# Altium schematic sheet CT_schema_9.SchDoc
size 277 x 170 mm
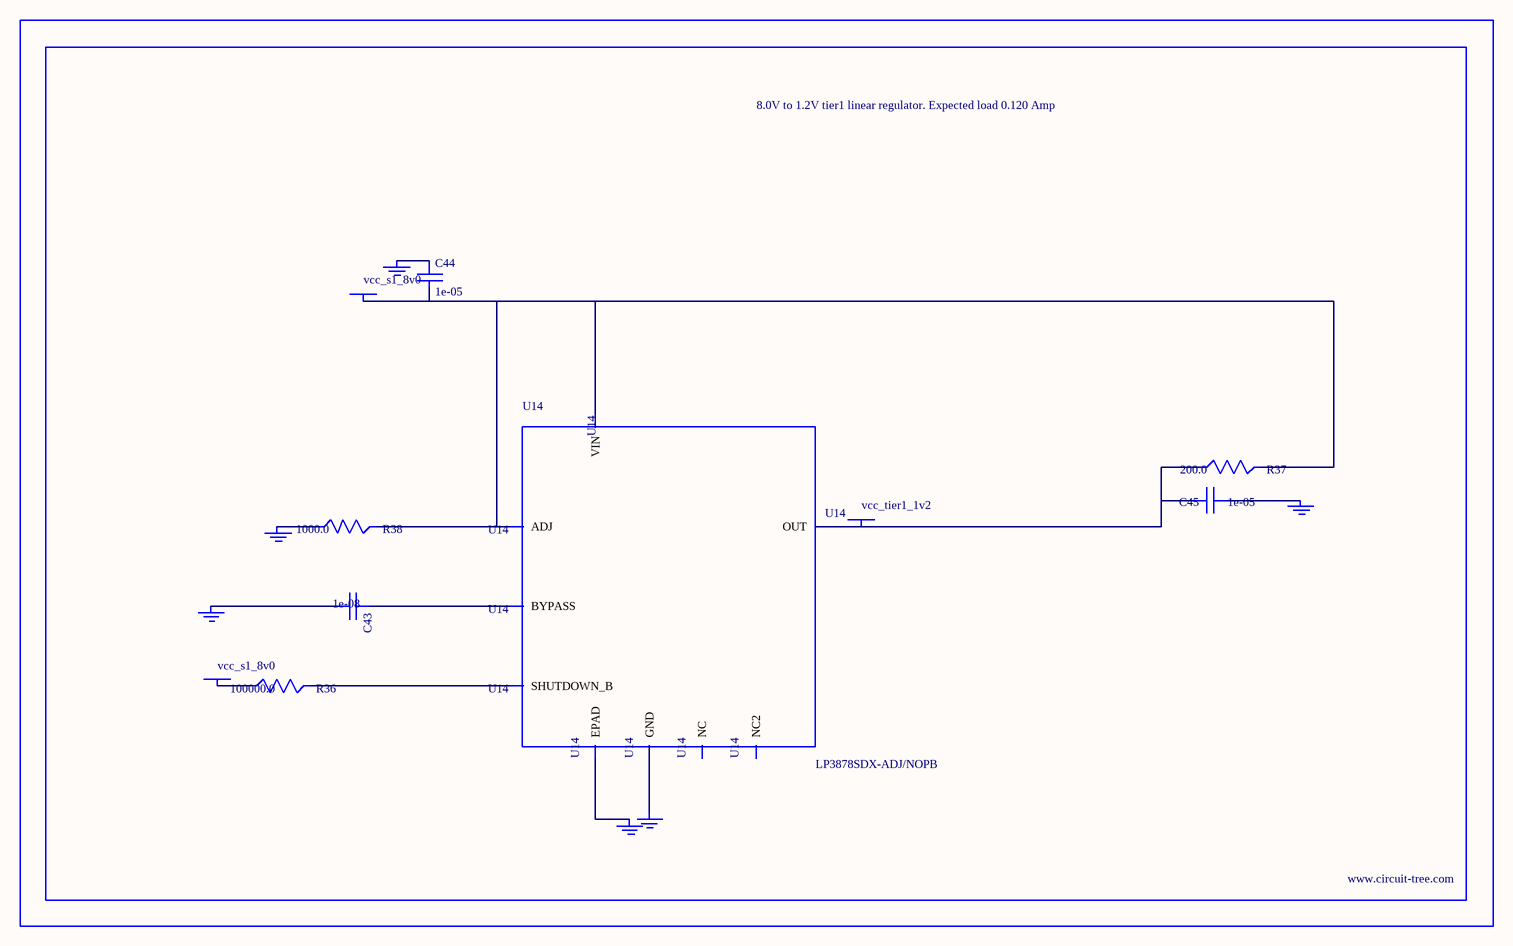
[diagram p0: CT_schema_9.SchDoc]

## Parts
BORDER8  (no value)
C43  1e-08  [C0402]
C44  1e-05  [C1206]
C45  1e-05  [C0805]
GND_INSTANCE_8_0  (no value)
GND_INSTANCE_8_1  (no value)
GND_INSTANCE_8_2  (no value)
GND_INSTANCE_8_3  (no value)
GND_INSTANCE_8_4  (no value)
GND_INSTANCE_8_5  (no value)
POWER_INSTANCE_8_0  vcc_s1_8v0
POWER_INSTANCE_8_1  vcc_s1_8v0
POWER_INSTANCE_8_2  vcc_tier1_1v2
R36  100000.0  [R0603]
R37  200.0  [R0603]
R38  1000.0  [R0603]
U14  LP3878SDX-ADJ/NOPB  [WSON-8]

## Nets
NetC43_1: C43.1 U14.1(BYPASS)
NetC43_2: C43.2 GND_INSTANCE_8_0.0(GND)
NetC44_1: C44.1 GND_INSTANCE_8_1.0(GND)
NetC44_2: C44.2 POWER_INSTANCE_8_0.0(PWR) R37.2 R38.2 U14.4(VIN) U14.6(ADJ)
NetC45_1: C45.1 GND_INSTANCE_8_2.0(GND)
NetC45_2: C45.2 POWER_INSTANCE_8_2.0(PWR) R37.1 U14.5(OUT)
NetGND_INSTANCE_8_3_0: GND_INSTANCE_8_3.0(GND) R38.1
NetGND_INSTANCE_8_4_0: GND_INSTANCE_8_4.0(GND) U14.PAD(EPAD)
NetGND_INSTANCE_8_5_0: GND_INSTANCE_8_5.0(GND) U14.3(GND)
NetPOWER_INSTANCE_8_1_0: POWER_INSTANCE_8_1.0(PWR) R36.1
NetR36_2: R36.2 U14.8(SHUTDOWN_B)

Not connected (* = marked no-connect by the designer): U14 2(NC) 7(NC2)

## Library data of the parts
BORDER8 = BORDER_PAGE8
C43 = C0402C103K3RAC
C44 = C1206C106K3RACTU
C45 = GRM219R60J106ME19D
GND_INSTANCE_8_0-GND_INSTANCE_8_5 = GND
POWER_INSTANCE_8_0-POWER_INSTANCE_8_2 = PWR
R36 = RC0603JR-07100KL
R37 = RC0603JR-07200RL
R38 = RC0603JR-071KL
